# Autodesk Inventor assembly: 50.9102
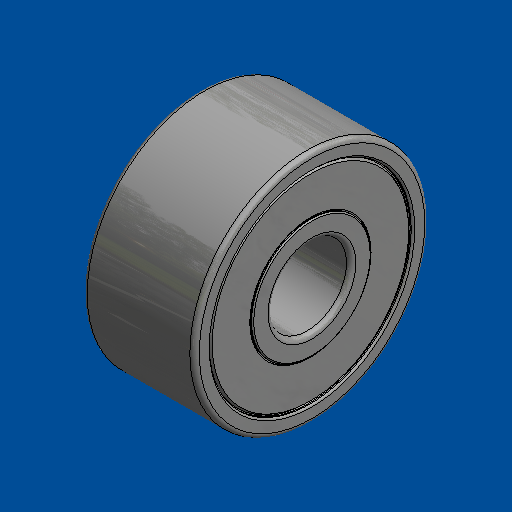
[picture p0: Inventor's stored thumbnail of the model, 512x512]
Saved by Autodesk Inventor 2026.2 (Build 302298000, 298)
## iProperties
Company: CADENAS
Created: 2022-08
Part Number: 50.9102
Description: 5200 2RS DOUBLE ROW ANGULAR CONTACT BEARING
Document SubType Name: Assembly
Designer: amoles
Vendor: S
Sending System: PARTsolutions
Preprocessor: ST-DEVELOPER v18.102
Title: 5200 2RS
Author: License CC BY-ND 4.0
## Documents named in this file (5)
- L:\INVENTOR LIBRARIES\PARTS LIBRARY\MACHINE ELEMENTS\BALL BEARINGS\50.9102 5200 2RS DOUBLE ROW ANGULAR CONTACT BEARING 10mm ID - 30MM OD.iam
- L:\INVENTOR LIBRARIES\PARTS LIBRARY\MACHINE ELEMENTS\BALL BEARINGS\SUBCOMPONENTS\50.9102 5200 2RS-Seal.ipt
- L:\INVENTOR LIBRARIES\PARTS LIBRARY\MACHINE ELEMENTS\BALL BEARINGS\SUBCOMPONENTS\50.9102 5200 2RS-Ball.ipt
- L:\INVENTOR LIBRARIES\PARTS LIBRARY\MACHINE ELEMENTS\BALL BEARINGS\SUBCOMPONENTS\50.9102 5200 2RS-Outer Ring.ipt
- L:\INVENTOR LIBRARIES\PARTS LIBRARY\MACHINE ELEMENTS\BALL BEARINGS\SUBCOMPONENTS\50.9102 5200 2RS-Inner Ring.ipt
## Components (18 placed, 18 different names)
1. NAUO1
2. NAUO2
3. NAUO3
4. NAUO4
5. NAUO5
6. NAUO6
7. NAUO7
8. NAUO8
9. NAUO9
10. NAUO10
11. NAUO11
12. NAUO12
13. NAUO13
14. NAUO14
15. NAUO15
16. NAUO16
17. NAUO17
18. NAUO18
